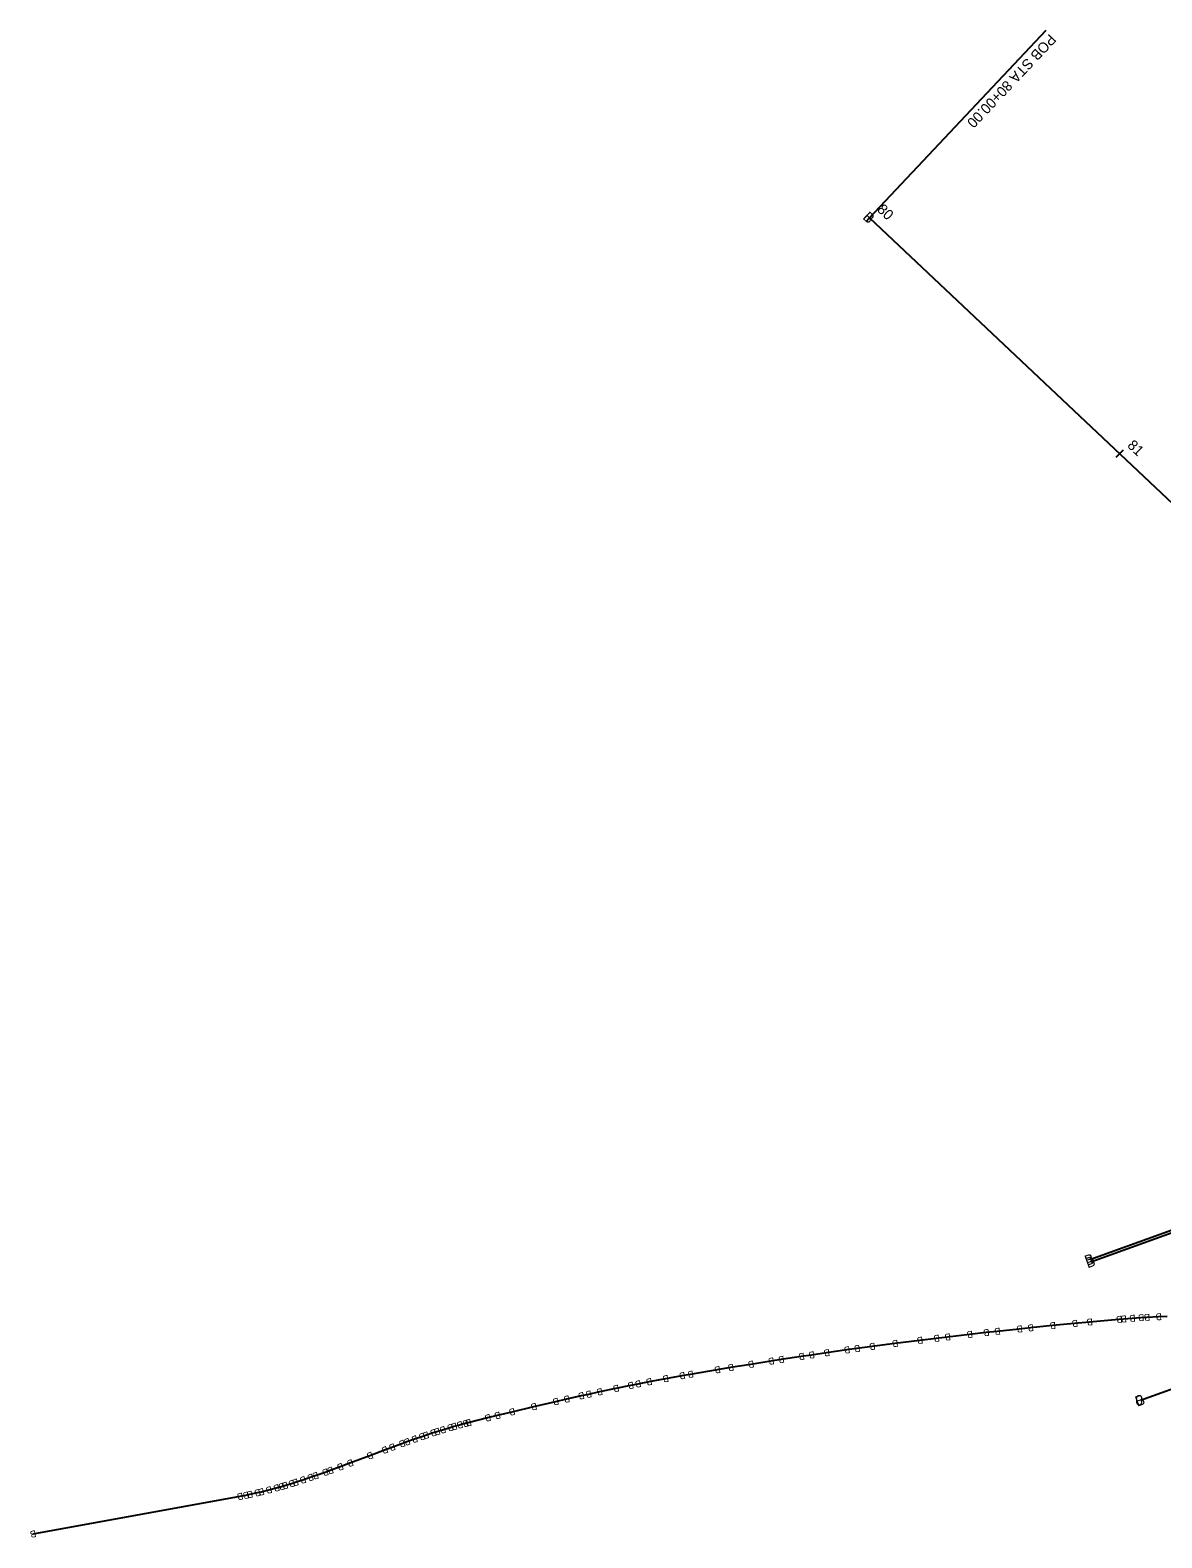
# Model space of a CAD drawing. Extents: x 74655 to 77873, y 48844 to 50507.
# Drawn here: x 74655.4 to 74984.6, y 49633 to 50071.3 of the extents above; entities that cross this region are included whole.
import ezdxf

# ---------------------------------------------------------------- set-up
doc = ezdxf.new("R2010")
doc.units = 0
for name, color, linetype in [('14', 7, 'Continuous'), ('2', 7, 'Continuous'), ('33', 7, 'Continuous'), ('6', 7, 'Continuous'), ('61', 7, 'Continuous'), ('62', 7, 'Continuous'), ('7', 7, 'Continuous')]:
    doc.layers.add(name, color=color, linetype=linetype)

msp = doc.modelspace()

# ---------------------------------------------------------------- linework, layer by layer
at = {"layer": '14'}
for p, q in [((74972.1, 49696.51), (74963.5, 49695.73)), ((74973.37, 49696.62), (74972.1, 49696.51)), ((74975.92, 49696.82), (74973.37, 49696.62)), ((74978.46, 49696.99), (74975.92, 49696.82)), ((74980.16, 49697.09), (74978.46, 49696.99)), ((74983.56, 49697.27), (74980.16, 49697.09)), ((74986.11, 49697.38), (74983.56, 49697.27)), ((74928.61, 49692.13), (74922.18, 49691.38)), ((74933.44, 49692.67), (74928.61, 49692.13)), ((74936.66, 49693.03), (74933.44, 49692.67)), ((74943.1, 49693.71), (74936.66, 49693.03)), ((74946.32, 49694.05), (74943.1, 49693.71)), ((74952.76, 49694.7), (74946.32, 49694.05)), ((74959.2, 49695.33), (74952.76, 49694.7)), ((74963.5, 49695.73), (74959.2, 49695.33)), ((74895.86, 49688.03), (74892.92, 49687.62)), ((74900.28, 49688.63), (74895.86, 49688.03)), ((74906.91, 49689.5), (74900.28, 49688.63)), ((74914.14, 49690.41), (74906.91, 49689.5)), ((74918.97, 49691), (74914.14, 49690.41)), ((74922.18, 49691.38), (74918.97, 49691)), ((74865.01, 49683.44), (74859.14, 49682.5)), ((74870.88, 49684.37), (74865.01, 49683.44)), ((74873.81, 49684.82), (74870.88, 49684.37)), ((74879.69, 49685.71), (74873.81, 49684.82)), ((74882.62, 49686.15), (74879.69, 49685.71)), ((74887.03, 49686.79), (74882.62, 49686.15)), ((74892.92, 49687.62), (74887.03, 49686.79)), ((74840.17, 49679.25), (74835.36, 49678.34)), ((74845, 49680.12), (74840.17, 49679.25)), ((74847.41, 49680.53), (74845, 49680.12)), ((74855.23, 49681.85), (74847.41, 49680.53)), ((74859.14, 49682.5), (74855.23, 49681.85)), ((74817.77, 49674.73), (74815.64, 49674.27)), ((74820.96, 49675.42), (74817.77, 49674.73)), ((74825.75, 49676.43), (74820.96, 49675.42)), ((74830.02, 49677.3), (74825.75, 49676.43)), ((74832.15, 49677.72), (74830.02, 49677.3)), ((74835.36, 49678.34), (74832.15, 49677.72)), ((74801.85, 49671.11), (74795.49, 49669.59)), ((74808.21, 49672.59), (74801.85, 49671.11)), ((74811.39, 49673.32), (74808.21, 49672.59)), ((74815.64, 49674.27), (74811.39, 49673.32)), ((74780.31, 49665.8), (74778.65, 49665.34)), ((74781.97, 49666.24), (74780.31, 49665.8)), ((74782.81, 49666.46), (74781.97, 49666.24)), ((74788.44, 49667.87), (74782.81, 49666.46)), ((74791.26, 49668.56), (74788.44, 49667.87)), ((74795.49, 49669.59), (74791.26, 49668.56)), ((74767.15, 49661.66), (74764.98, 49660.89)), ((74769.32, 49662.41), (74767.15, 49661.66)), ((74770.41, 49662.78), (74769.32, 49662.41)), ((74772.6, 49663.5), (74770.41, 49662.78)), ((74773.69, 49663.85), (74772.6, 49663.5)), ((74775.34, 49664.36), (74773.69, 49663.85)), ((74777.54, 49665.02), (74775.34, 49664.36)), ((74778.65, 49665.34), (74777.54, 49665.02)), ((74758.48, 49658.49), (74754.17, 49656.86)), ((74760.65, 49659.3), (74758.48, 49658.49)), ((74763.53, 49660.36), (74760.65, 49659.3)), ((74764.98, 49660.89), (74763.53, 49660.36)), ((74745.54, 49653.61), (74742.65, 49652.55)), ((74748.42, 49654.68), (74745.54, 49653.61)), ((74754.17, 49656.86), (74748.42, 49654.68)), ((74731.4, 49648.76), (74729.45, 49648.17)), ((74732.5, 49649.1), (74731.4, 49648.76)), ((74734.69, 49649.79), (74732.5, 49649.1)), ((74736.87, 49650.52), (74734.69, 49649.79)), ((74738.32, 49651.01), (74736.87, 49650.52)), ((74741.21, 49652.03), (74738.32, 49651.01)), ((74742.65, 49652.55), (74741.21, 49652.03)), ((74716.39, 49645.03), (74656.16, 49634.09)), ((74718.08, 49645.35), (74716.39, 49645.03)), ((74719.21, 49645.58), (74718.08, 49645.35)), ((74721.45, 49646.07), (74719.21, 49645.58)), ((74722.56, 49646.33), (74721.45, 49646.07)), ((74724.79, 49646.88), (74722.56, 49646.33)), ((74727, 49647.47), (74724.79, 49646.88)), ((74728.47, 49647.89), (74727, 49647.47)), ((74729.45, 49648.17), (74728.47, 49647.89))]:
    msp.add_line(p, q, dxfattribs=at)
at = {"layer": '2'}
msp.add_line((74899.49, 50016.71), (75055.37, 49869.8), dxfattribs=at)
at = {"layer": '33'}
for points in [[(74899.49, 50016.71), (74950.92, 50071.29)], [(74900.51, 50017.8), (74898.46, 50015.62)], [(74973.29, 49949.22), (74971.23, 49947.03)]]:
    msp.add_lwpolyline(points, dxfattribs=at)
at = {"layer": '6'}
msp.add_line((74978.35, 49673.03), (75354.83, 49808.15), dxfattribs=at)
at = {"layer": '7'}
for p, q in [((74963.65, 49713.97), (75340.14, 49849.09)), ((74963.91, 49713.27), (75340.39, 49848.38))]:
    msp.add_line(p, q, dxfattribs=at)

# ---------------------------------------------------------------- texts
at = {"layer": '2'}
msp.add_text('B', height=3, rotation=316.6979, dxfattribs=at).set_placement((74897.36, 50016.65))
at = {"layer": '33'}
for s, rotation, p in [('POB STA 80+00.00', 226.6979, (74951.91, 50070.37)), ('80', 316.6979, (74901.54, 50018.89)), ('81', 316.6979, (74974.32, 49950.31))]:
    msp.add_text(s, height=3, rotation=rotation, dxfattribs=at).set_placement(p)
at = {"layer": '6'}
msp.add_text('B', height=3, rotation=19.7423, dxfattribs=at).set_placement((74977.44, 49671.11))
at = {"layer": '61'}
for rotation, p in [(185.1979, (74964.41, 49696.82)), (184.907, (74973.01, 49697.6)), (184.436, (74974.29, 49697.7)), (183.8592, (74976.85, 49697.89)), (183.4242, (74979.4, 49698.05)), (182.964, (74981.11, 49698.14)), (182.4993, (74984.52, 49698.31)), (186.8006, (74919.84, 49692.11)), (186.6184, (74923.06, 49692.49)), (186.4107, (74929.5, 49693.24)), (186.2658, (74934.33, 49693.78)), (186.0962, (74937.55, 49694.13)), (185.9303, (74943.99, 49694.81)), (185.7692, (74947.21, 49695.14)), (185.5605, (74953.66, 49695.79)), (185.3922, (74960.1, 49696.42)), (188.0684, (74887.88, 49687.92)), (187.8827, (74893.77, 49688.75)), (187.7255, (74896.72, 49689.15)), (187.4857, (74901.14, 49689.75)), (187.1943, (74907.78, 49690.62)), (186.9559, (74915.01, 49691.53)), (189.1727, (74859.97, 49683.64)), (188.9508, (74865.84, 49684.59)), (188.7808, (74871.71, 49685.51)), (188.6073, (74874.65, 49685.96)), (188.4309, (74880.53, 49686.85)), (188.2814, (74883.47, 49687.28)), (190.6421, (74836.16, 49679.51)), (190.1839, (74840.98, 49680.41)), (189.825, (74845.81, 49681.27)), (189.5642, (74848.23, 49681.69)), (189.3533, (74856.06, 49683)), (192.3608, (74816.4, 49675.46)), (192.1696, (74818.53, 49675.92)), (191.8681, (74821.73, 49676.6)), (191.5065, (74826.53, 49677.61)), (191.2383, (74830.8, 49678.47)), (191.0056, (74832.94, 49678.89)), (193.4537, (74796.23, 49670.8)), (193.1081, (74802.59, 49672.31)), (192.8211, (74808.96, 49673.79)), (192.5792, (74812.15, 49674.51)), (196.0691, (74778.23, 49666.26)), (195.5307, (74779.34, 49666.57)), (194.8479, (74781.02, 49667.03)), (194.3099, (74782.7, 49667.46)), (194.0251, (74783.54, 49667.67)), (193.8615, (74789.18, 49669.08)), (193.7088, (74792, 49669.77)), (199.8817, (74764.13, 49661.64)), (199.5477, (74765.58, 49662.16)), (199.0813, (74767.77, 49662.93)), (198.6854, (74769.95, 49663.68)), (198.2432, (74771.05, 49664.04)), (197.764, (74773.25, 49664.76)), (197.3299, (74774.35, 49665.1)), (196.6734, (74776.01, 49665.61)), (200.7276, (74754.75, 49658.15)), (200.5052, (74759.07, 49659.78)), (200.209, (74761.24, 49660.59)), (199.7766, (74741.81, 49653.31)), (200.1247, (74743.25, 49653.83)), (200.4797, (74746.12, 49654.89)), (200.7516, (74749, 49655.97)), (195.6778, (74727.7, 49648.71)), (196.152, (74729.16, 49649.13)), (196.688, (74730.12, 49649.42)), (197.2146, (74732.06, 49650.01)), (197.7387, (74733.15, 49650.35)), (198.3753, (74735.32, 49651.06)), (198.8505, (74737.49, 49651.79)), (199.3466, (74738.93, 49652.29)), (190.7513, (74717.19, 49646.2)), (191.4986, (74718.87, 49646.53)), (192.3552, (74719.97, 49646.77)), (193.1758, (74722.19, 49647.27)), (193.9508, (74723.29, 49647.54)), (194.9227, (74725.5, 49648.11)), (190.292, (74656.97, 49635.26))]:
    msp.add_text('B', height=2, rotation=rotation, dxfattribs=at).set_placement(p)
at = {"layer": '62'}
msp.add_text('0', height=3, dxfattribs=at).set_placement((74976.85, 49671.53))
at = {"layer": '7'}
for p in [(74962.75, 49712.05), (74963, 49711.35)]:
    msp.add_text('B', height=3, rotation=19.7423, dxfattribs=at).set_placement(p)

doc.saveas('drawing.dxf')
